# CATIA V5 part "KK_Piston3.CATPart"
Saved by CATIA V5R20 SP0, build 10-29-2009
Part number: Piston3
Bounding box of the stored display mesh (mm): x 58.397 to 90.943, y -18.259 to -0.352, z 33.905 to 105
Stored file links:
  G:\Khaled_CFAO_2011\ST2M\ST2M_GR1\msallin\Khaled\Version_Finale\KK_Piston3.CATPart
  C:\Users\Mathieu\Desktop\Think Motion\JOUG-MELEE2.CATProduct
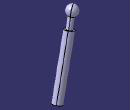
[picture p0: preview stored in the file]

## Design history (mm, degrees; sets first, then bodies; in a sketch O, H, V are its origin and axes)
External parameters (linked from other documents)
  `External.Taille du joug` = 100 mm
Set1
  Line1: linked copy from another document
  Line2: linked copy from another document
  Point1: linked copy from another document
  Point2: linked copy from another document
Set2
  Plane1: type 2Lines, Element1 Line1, Element2 Line2
Body1 (main body)
  Sketch1 on Plane1, origin (70.7263, -40.514, 20.3771), H (0.4971, 0.8677, 0), V (-0.2105, 0.1206, 0.9701)
    point P1 (39.3742, 15.5054)
    line L1 (39.3742, 15.5054) -> (43.3748, 16.6697)
    line L2 (43.3748, 16.6697) -> (28.0052, 69.4786)
    line L3 (28.0052, 69.4786) -> (26.4049, 69.0128)
    line L4 (26.4049, 69.0128) -> (23.6104, 78.6144)
    arc A1 centre (20, 82.0734) radius 5 from (23.6104, 78.6144) to (18.6028, 86.8742) ccw
    point P6 (20, 82.0734)
    point P7 (18.6028, 86.8742)
    reference projected line E1 (20, 82.0734) -> (50, -21.0042) from Line2
    reference projected line E2 (20, 82.0734) -> (50, -21.0042) from Line2
    reference projected line E3 (20, 82.0734) -> (50, -21.0042) from Line2
    reference projected point E4 (20, 82.0734) from Point1
    reference projected line E5 (20, 82.0734) -> (50, -21.0042) from Line2
    distance P1 E1 = 0
    distance L2 E2 = 4.1667 {= `External.Taille du joug` /24}
    distance L4 E3 = 2.5 {= `External.Taille du joug` /40}
    length L2 = 55 {= `External.Taille du joug` *(7/10-1/10-1/20)}
    length L4 = 10 {= `External.Taille du joug` /10}
    distance P6 E4 = 0
    distance E5 P7 = 0
    radius A1 = 5 {= `External.Taille du joug` /20}
    perpendicularity: L2 L1
    parallelism: L3 L1, L4 L2
  Shaft1: profile Sketch1, axis Line2, angle 360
